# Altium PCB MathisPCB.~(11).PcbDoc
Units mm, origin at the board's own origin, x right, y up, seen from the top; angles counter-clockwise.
Board outline 17.02 x 14.1 mm, 2 copper layers (Top Layer, Bottom Layer); 8 components, 10 nets, 25 pads, 0 vias.
Unrouted connection lines stored in the file: 15.
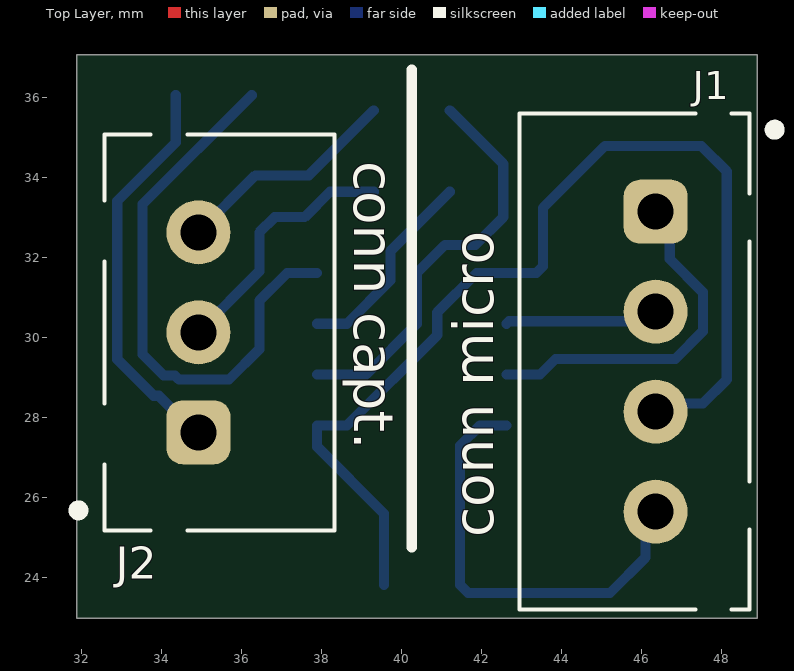
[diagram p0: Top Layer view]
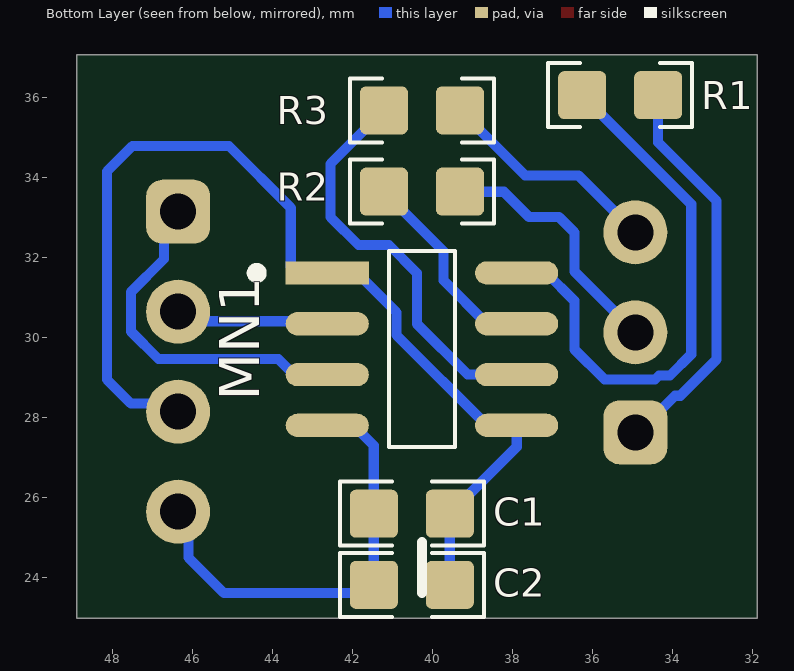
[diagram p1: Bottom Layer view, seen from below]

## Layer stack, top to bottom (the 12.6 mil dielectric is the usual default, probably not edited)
Top Solder: solder mask 0.0102, Solder Resist, Dk 3.5
Top Layer: signal copper 0.0356
Dielectric 1: dielectric 0.32, FR-4, Dk 4.8
Bottom Layer: signal copper 0.0356
Bottom Solder: solder mask 0.0102, Solder Resist, Dk 3.5

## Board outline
31.877,22.987 31.877,37.084 48.895,37.084 48.895,22.987

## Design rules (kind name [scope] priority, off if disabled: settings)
Clearance [All] p1: gap=0.254 ignorepadtopadclearanceinfootprint=FALSE except(0: Arc-Hole Track-Hole SMDPad-Hole THPad-Hole Via-Hole Fill-Hole Poly-Hole Region-Hole Text-Hole)
PolygonConnect [All] p1: connectstyle=Relief reliefconductorwidth=0.254 reliefentries=4 polygonreliefangle="90 Angle" airgapwidth=0.254
RoutingVias [All] p1: holewidth=0.711 width=1.27 viastyle="Through Hole" minholewidth=0.711 minwidth=1.27 maxholewidth=0.711 maxwidth=1.27
SolderMaskExpansion [All] p1: expansion=0.102 istentingtop=FALSE
Width [All] p1: maxlimit=0.254 minlimit=0.254 preferedwidth=0.254
30 further rules are at their usual default settings.

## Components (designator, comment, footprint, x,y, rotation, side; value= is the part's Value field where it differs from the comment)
C1 "MCU0805R104KCT" CAP_0805 40.513,25.654 r0 bottom value=100nF
C2 "GRM21BR71H105KA12L" CAP_0805 40.513,23.876 r0 bottom value=1uF
J1 "B4B-XH-A(LF)(SN)" B4B-XH-A 46.355,29.404 r270 top
J2 "B3B-XH-A(LF)(SN)" B3B-XH-A 34.925,30.139 r90 top
MN1 "CAP1203-1-SN" FP-C04-057-SN-IPC_B 40.259,29.718 r180 bottom
R1 "CRCW08054K70FKEA" RES_0805 35.306,36.068 r180 bottom
R2 "CRCW08054K70FKEA" RES_0805 40.259,33.655 r180 bottom
R3 "CRCW08054K70FKEA" RES_0805 40.259,35.687 r0 bottom

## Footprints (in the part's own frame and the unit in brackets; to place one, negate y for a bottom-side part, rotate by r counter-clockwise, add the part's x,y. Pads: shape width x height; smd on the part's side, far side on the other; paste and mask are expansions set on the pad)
B3B-XH-A [mm] "JST XH 3pts 2.5mm"
  rrect50% 1.6x1.6 hole 0.9: 1(-2.5,0)
  round 1.6 hole 0.9: 2(0,0) 3(2.5,0)
  silkscreen extent -4.95,-3.4 4.95,3.1, body extent -4.95,-3.41 4.95,2.35, height 7
B4B-XH-A [mm] "JST XH 4pts 2.5mm"
  rrect50% 1.6x1.6 hole 0.9: 1(-3.75,0)
  round 1.6 hole 0.9: 2(-1.25,0) 3(1.25,0) 4(3.75,0)
  silkscreen extent -6.2,-3.4 6.2,3.08, body extent -6.2,-3.37 6.2,2.38, height 7
CAP_0805 [mm] "Capacitor 0805"
  rrect25% 1.2x1.2 smd: 1(-0.95,0.05) 2(0.95,0.05)
  silkscreen extent -1.8,-0.75 1.8,0.85, body extent -1,-0.58 1,0.67, height 0.81
FP-C04-057-SN-IPC_B [mm]
  rect 2.077x0.582 smd paste+0 mask+0: 1(-2.368,1.905)
  rrect100% 2.077x0.582 smd paste+0 mask+0: 2(-2.368,0.635) 3(-2.368,-0.635) 4(-2.368,-1.905) 5(2.368,-1.905) 6(2.368,-0.635) 7(2.368,0.635) 8(2.368,1.905)
  silkscreen extent -4.26,-2.45 0.83,2.45, body extent -3,-2.45 3,2.45, height 1.75
RES_0805 [mm] "0805 resistors"
  rrect25% 1.2x1.2 smd: 1(-0.95,0) 2(0.95,0)
  silkscreen extent -1.8,-0.8 1.8,0.8, body extent -1,-0.6 1,0.6, height 0.55

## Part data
C1: library part U0805R104KCT-1, "Cap Ceramic 0.1uF 50V X7R ±10% SMD 0805 125°C T/R", Case Code (Imperial)=0805, Case Code (Metric)=2012, Dielectric=X7R, Max Operating Temperature=125°C, Min Operating Temperature=-55°C, Tolerance=10%, Voltage Rating=50V
C2: library part GRM21BR71H105KA12L-1, "0805 1 uF 50 V ±10% Tolerance X7R Multilayer Ceramic Chip Capacitor", Case Code (Imperial)=0805, Case Code (Metric)=2012, Dielectric=X7R, Max Operating Temperature=125°C, Min Operating Temperature=-55°C, Package Quantity=1, Tolerance=10%, Voltage=50V
J1: library part CMP-047-000046-2, "JST Connector Header, XH Series, 4 Positions, 2.5mm Pitch Through Hole Crimp Top Entry Shrouded Header", Color=Natural, Contact Resistance=20mR, Current Rating=3A, Flammability Rating="UL94 V-0", Housing Color=White, Insulation Resistance=1GR, Manufacturer=JST, Max Operating Temperature=85°C, Max Voltage Rating (AC)=250V, Min Operating Temperature=-25°C, Package Quantity=500
J2: library part CMP-047-000044-2, "JST Connector Header, XH Series, 3 Positions, 2.50mm, Through Hole, Press-Fit, Solder, Natural", Manufacturer=JST
MN1: library part CMP-000015-1, "Touch Sensor Capacitive 3 Key 3V to 5.5V SMD 8-Pin SOIC Tube", Case/Package=SOIC, Max Operating Temperature=125°C, Min Operating Temperature=-40°C, Operating Supply Current=750uA
R1 R2 R3: library part CMP-079-000100-3, "Resistor Thick Film 0805 4.7K Ohm 1% ±100ppm/°C Molded SMD SMD Paper T/R", Resistance=4.7K

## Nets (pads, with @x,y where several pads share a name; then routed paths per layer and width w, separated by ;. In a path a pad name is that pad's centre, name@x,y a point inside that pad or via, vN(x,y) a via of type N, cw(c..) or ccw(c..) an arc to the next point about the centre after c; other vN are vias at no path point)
+5V: C1.2 C2.2 J1.4 MN1.4 | length 11.2
  Bottom Layer w0.254: MN1.4 41.968,27.813 41.463,27.308 C1.2 C2.2 41.667,23.622 45.212,23.622 46.097,24.507 46.097,25.396 J1.4
GND: C1.1 C2.1 J1.3 MN1.1 MN1.5 | length 26.6
  Bottom Layer w0.254: C2.1 C1.1 37.891,27.276 MN1.5 38.639,27.813 40.894,30.068 40.894,30.638 41.879,31.623 43.374,31.623 43.538,31.787 43.538,33.251 45.085,34.798 47.498,34.798 48.133,34.163 48.133,28.956 47.536,28.359 46.56,28.359 J1.3
NetJ1_1: J1.1 MN1.3 | length 8.8
  Bottom Layer w0.254: MN1.3 43.463,29.083 43.853,29.473 46.844,29.473 47.536,30.165 47.536,31.143 46.706,31.973 46.706,32.803 J1.1
NetJ1_2: J1.2 MN1.2 | length 3.9
  Bottom Layer w0.254: MN1.2 42.689,30.416 46.117,30.416 J1.2
NetJ2_1: J2.1 R1.2 | length 10
  Bottom Layer w0.254: R1.2 34.356,34.886 32.893,33.423 32.893,29.464 33.804,28.553 33.935,28.553 34.849,27.639 J2.1
NetJ2_2: J2.2 R2.2 | length 6.4
  Bottom Layer w0.254: J2.2 36.449,31.663 36.449,32.639 36.83,33.02 37.58,33.02 38.215,33.655 R2.2
NetJ2_3: J2.3 R3.1 | length 5.6
  Bottom Layer w0.254: J2.3 36.348,34.062 37.684,34.062 R3.1
NetMN1_6: MN1.6 R3.2 | length 10.2
  Bottom Layer w0.254: MN1.6 39.116,29.083 40.386,30.353 40.386,31.623 41.084,32.321 41.846,32.321 42.545,33.02 42.545,34.351 R3.2
NetMN1_7: MN1.7 R2.1 | length 5.1
  Bottom Layer w0.254: MN1.7 38.639,30.353 39.723,31.437 39.723,32.169 R2.1
NetMN1_8: MN1.8 R1.1 | length 14
  Bottom Layer w0.254: R1.1 33.528,33.34 33.528,29.591 34.058,29.061 34.333,29.061 34.436,28.958 35.689,28.958 36.449,29.718 36.449,30.928 37.144,31.623 MN1.8

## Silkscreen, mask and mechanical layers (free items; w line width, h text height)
Top Overlay:
  lines w0.254: 40.259,24.765 40.259,36.703
  text "conn capt." at 38.814,34.417 h1 r270
  text "conn micro" at 42.291,25.019 h1 r90
Bottom Overlay:
  lines w0.254: 40.259,23.622 40.259,24.892
Board Shape:
  the board outline again, w0.254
